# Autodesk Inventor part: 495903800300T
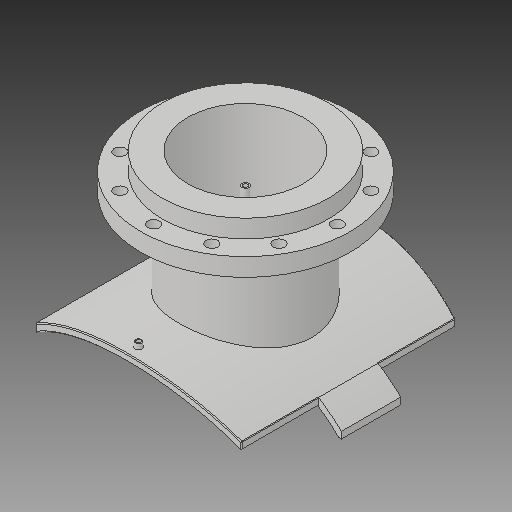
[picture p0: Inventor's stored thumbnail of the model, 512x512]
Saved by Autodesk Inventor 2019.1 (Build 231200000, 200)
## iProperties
Created: 2017-10
Part Number: 495903800300T
Material: Generic
Description: PLASSON FLANGED BRANCH SADDLE 800X300
Document SubType Name: Modeling
Designer: KIM
Mass: 2339.99 g
Surface Area: 3251.55 cm^2
Volume: 2339.99 cm^3
Density: 1 g/cm^3
Appearance: Default
Author: KIM
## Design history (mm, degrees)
derived "495904_495903.ipt"
feature "Solid1::495904_495903.ipt"
feature "Solid2::495904_495903.ipt"
tag "TaggingFeature1"
body "Solid1"
other parameters: "d1" = 15, "d2" = 459, "d4" = 0, "d6" = 132.5, "d7" = 0, "d12" = 425.6, "d13" = 14, "d14" = 238.5, "d16" = 5 deg, "d18" = 4, "d19" = 14, "d20" = 0, "d21" = 3, "d22" = 0, "d36" = 238.5, "d38" = 0, "d39" = 2, "d41" = 257, "d43" = 467, "d46" = 296, "d47" = 16, "d48" = 10.4, "d49" = 192.5, "d51" = 816, "d53" = 0, "d54" = 26, "d55" = 205, "d57" = 0, "d59" = 360 deg, "d63" = 0, "d66" = 275, "d67" = 15, "d68" = 137.5, "d70" = 0, "d71" = 2, "H_" = 275, "x_" = 15, "D_" = 16, "DN_" = 257, "D_1" = 467, "s_" = 26
